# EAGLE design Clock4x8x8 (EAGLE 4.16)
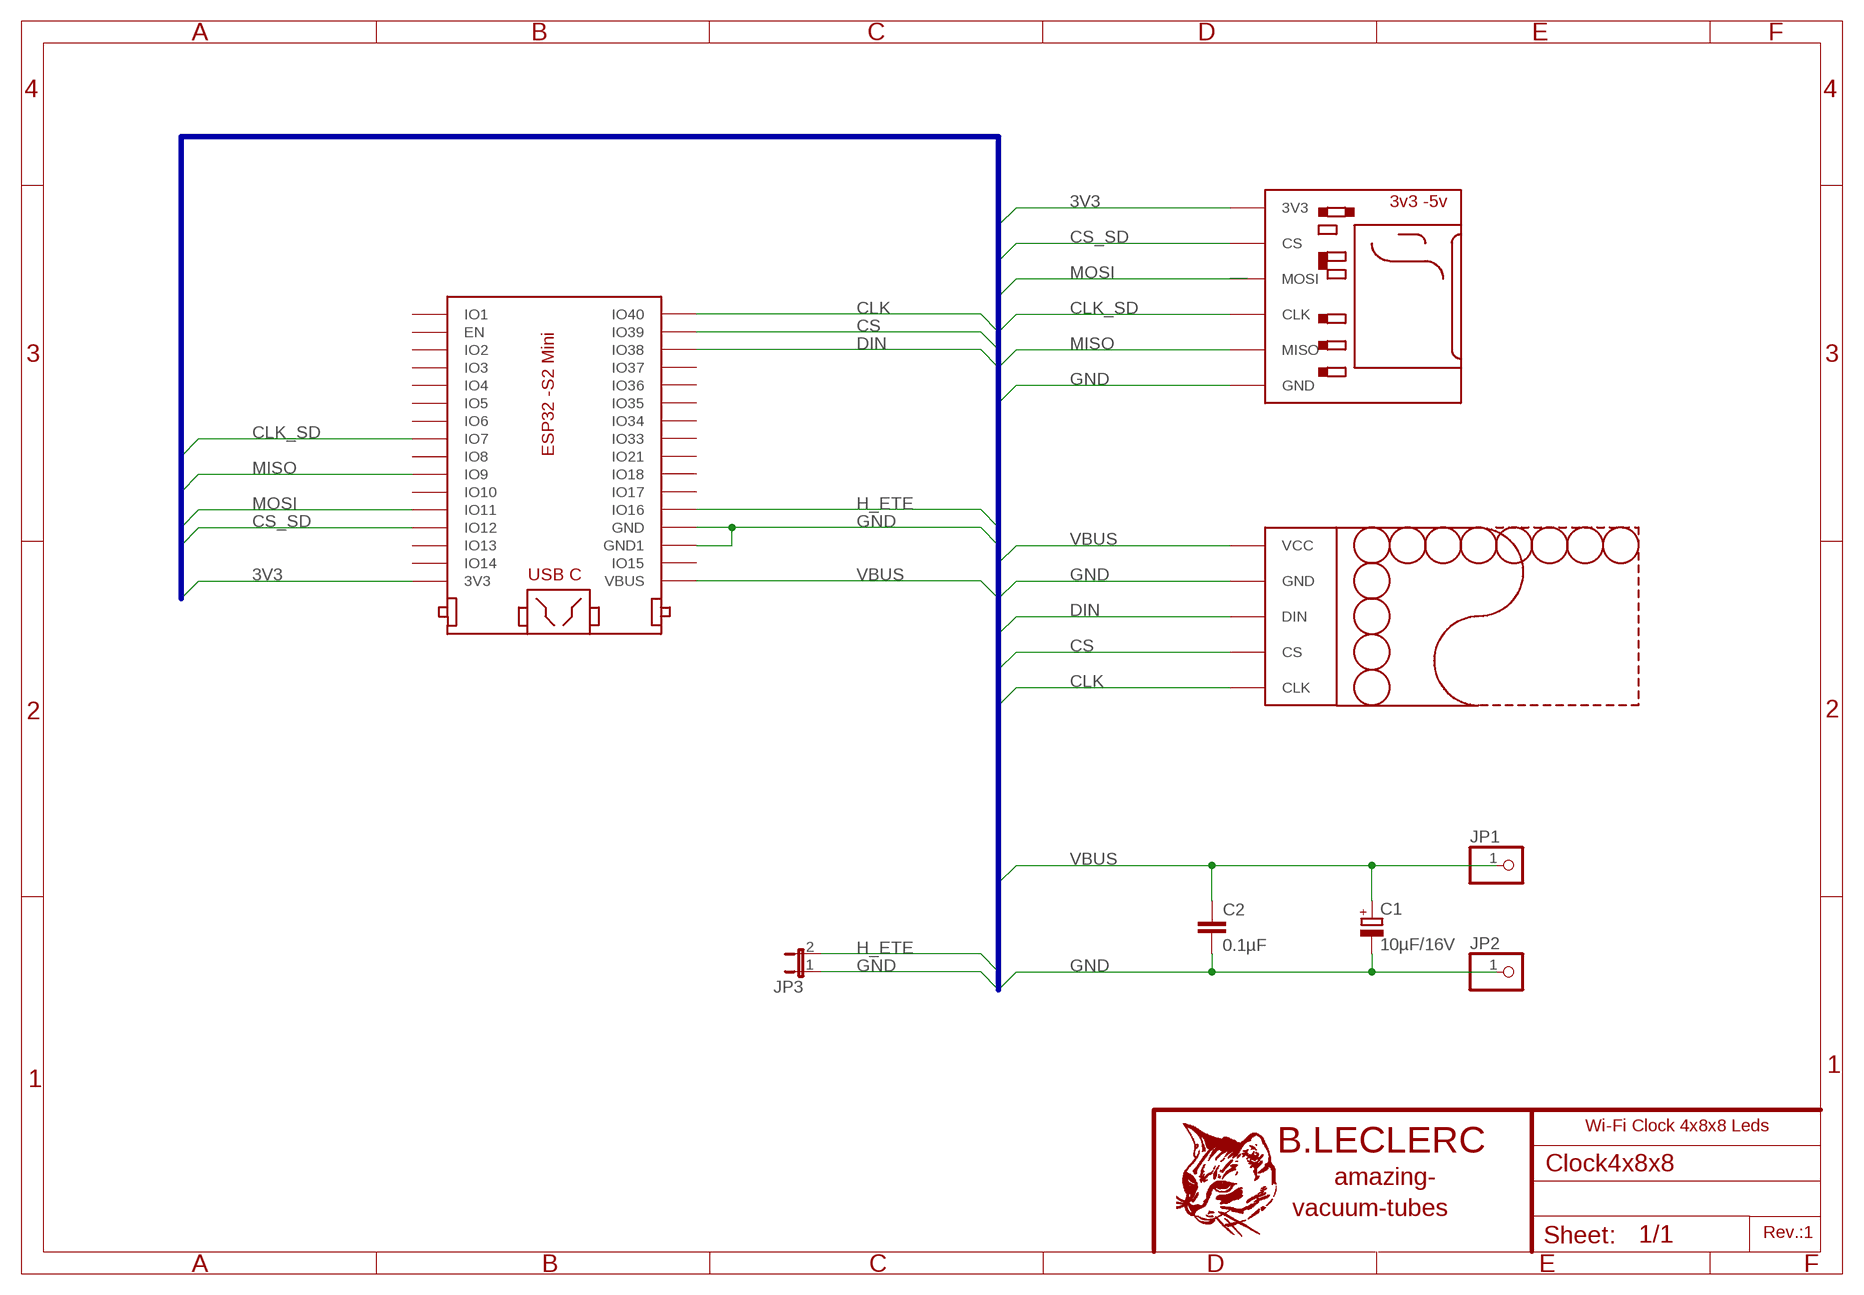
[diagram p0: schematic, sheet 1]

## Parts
C1  10µF/16V  CPOL-EUE5-8.5  [E5-8,5]
C2  0.1µF  C-EU102-043X133  [C102-043X133]
JP1  PINHD-1X1  [1X01]
JP2  PINHD-1X1  [1X01]
JP3  JP1E  [JP1]
U$2  ESP32_S2MINI  [ESP32_S2MINI]
U$3  LECTEUR_MICRO_SD  [LECTEUR_MICRO_SD]
U$4  4DIGITS_8X8_LEDS  [4DIGITS_8X8_LEDS]

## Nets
3V3: U$2.3V3 U$3.3V3
CLK: U$2.IO40 U$4.CLK
CLK_SD: U$2.IO7 U$3.CLK
CS: U$2.IO39 U$4.CS
CS_SD: U$2.IO12 U$3.CS
DIN: U$2.IO38 U$4.DIN
GND: C1.- C2.2 JP2.1 JP3.1 U$2.GND U$2.GND1 U$3.GND U$4.GND
H_ETE: JP3.2 U$2.IO16
MISO: U$2.IO9 U$3.MISO
MOSI: U$2.IO11 U$3.MOSI
VBUS: C1.+ C2.1 JP1.1 U$2.VBUS U$4.VCC
Unconnected: U$2.EN U$2.IO1 U$2.IO2 U$2.IO3 U$2.IO4 U$2.IO5 U$2.IO6 U$2.IO8 U$2.IO10 U$2.IO13 U$2.IO14 U$2.IO15 U$2.IO17 U$2.IO18 U$2.IO21 U$2.IO33 U$2.IO34 U$2.IO35 U$2.IO36 U$2.IO37

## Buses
B$1

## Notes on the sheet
- Wi-Fi Clock 4x8x8 Leds
- Rev.:1

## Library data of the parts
C1 = rcl:CPOL-EU: POLARIZED CAPACITOR, European symbol
C2 = rcl:C-EU: CAPACITOR, European symbol
JP1 JP2 = pinhead:PINHD-1X1: PIN HEADER
JP3 = jumper:JP1E: JUMPER
U$2 = Arduino:ESP32_S2MINI
U$3 = Arduino:LECTEUR_MICRO_SD
U$4 = Arduino:4DIGITS_8X8_LEDS

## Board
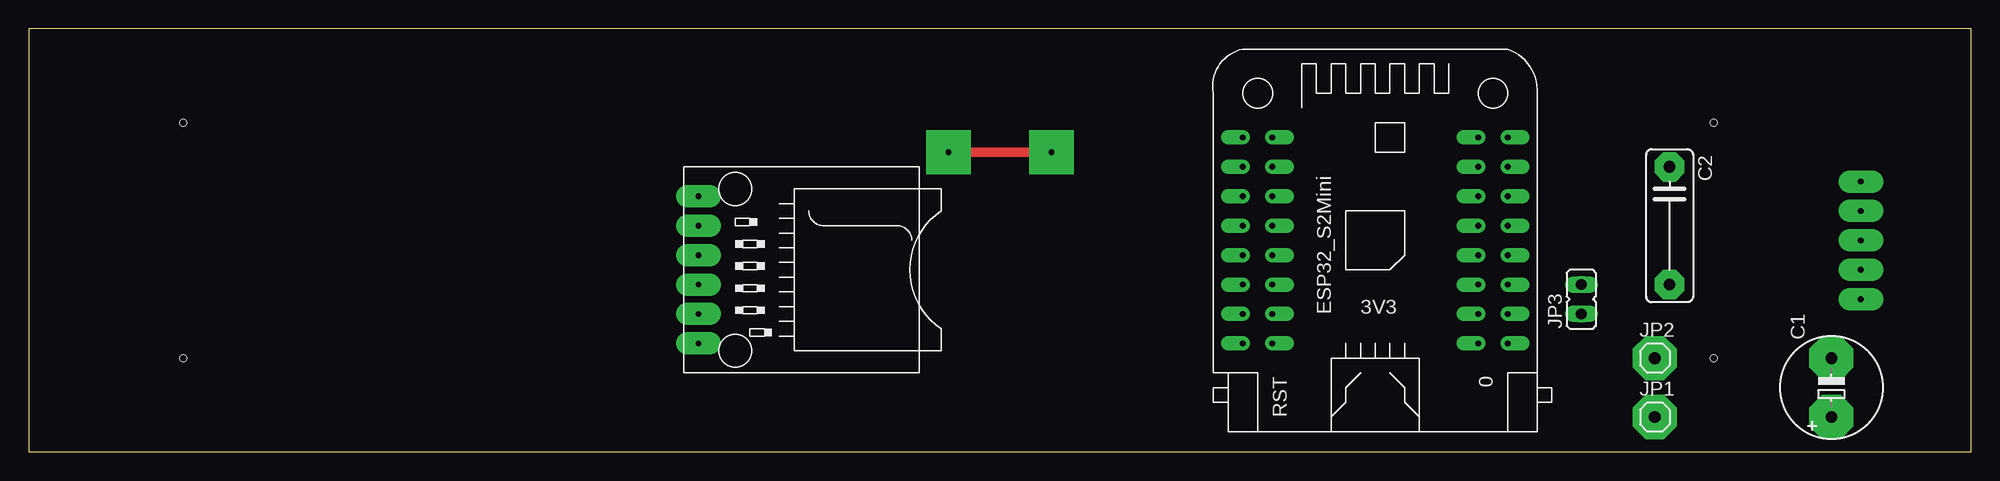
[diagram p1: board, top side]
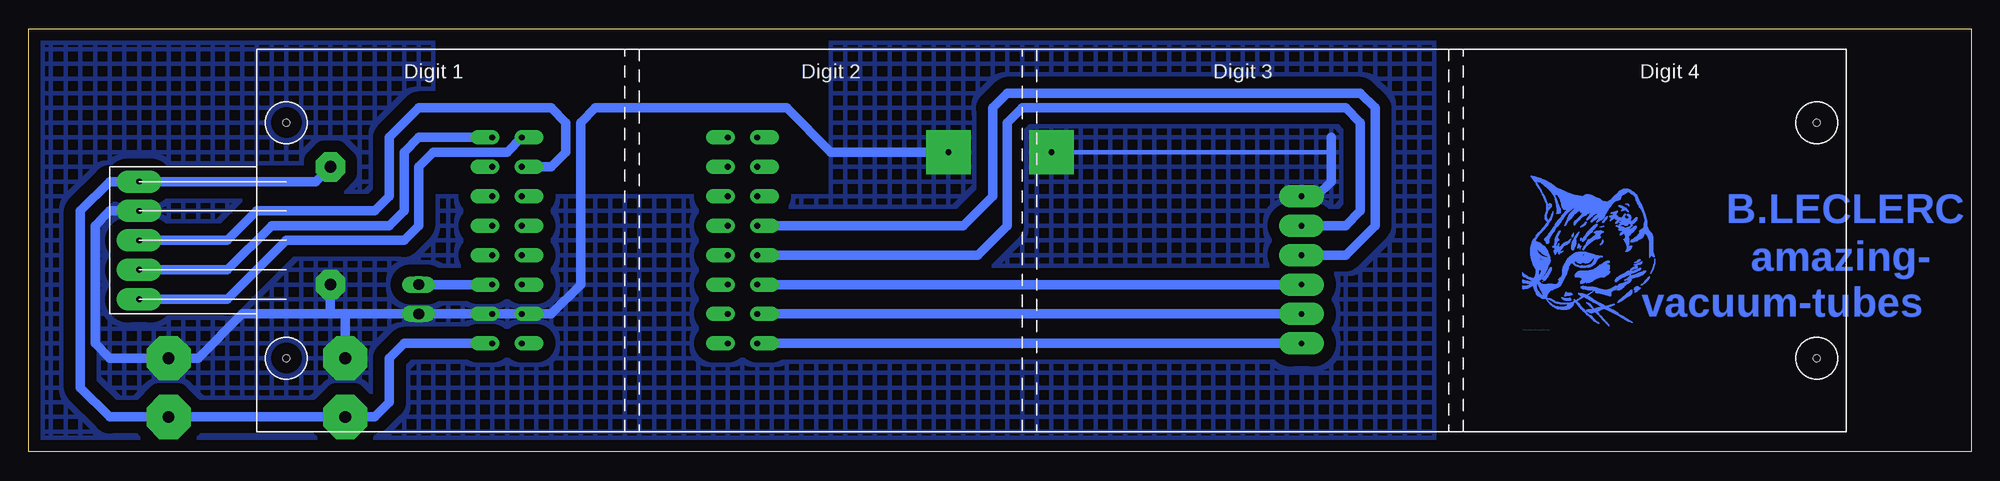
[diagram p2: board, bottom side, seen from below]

Size 167.62 x 36.5 mm. Coordinates in mm from the lower left corner, seen from the top.
Outline: 0,0 167.62,0 167.62,36.5 0,36.5 0,0
Copper layers (1*16): Top 0.035mm / dielectric 1.5mm / Bottom 0.035mm
Design rules "default": minimum track width 10mil, minimum drill 24mil, track to track 8mil, track to pad 8mil, pad to pad 8mil, via to via 8mil, smd to smd 8mil, copper to edge 40mil, drill to drill 8mil, minimum pad ring 10mil, minimum via ring 8mil, stop-mask expansion 4mil, vias tented up to drill 0mil, thermal gap 10mil

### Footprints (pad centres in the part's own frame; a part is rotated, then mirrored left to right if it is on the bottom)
E5-8,5 = drill 1.016 pad 2.54 round: + -2.54,0 | drill 1.016 pad 2.54 octagon: - 2.54,0
C102-043X133 = drill 1.016 octagon: 1 -5.08,0; 2 5.08,0
1X01 = drill 1.016 octagon: 1 0,0
JP1 = drill 0.914 long: 1 0,-1.27; 2 0,1.27
ESP32_S2MINI = drill 0.5 pad 1.27 offset: 3V3 0,0; EN 0,17.78; GND 20.32,2.54; GND1 22.86,2.54; IO1 2.54,17.78; IO2 2.54,15.24; IO3 0,15.24; IO4 2.54,12.7; IO5 0,12.7; IO6 2.54,10.16; IO7 0,10.16; IO8 2.54,7.62; IO9 0,7.62; IO10 2.54,5.08; IO11 0,5.08; IO12 0,2.54; IO13 2.54,2.54; IO14 2.54,0; IO15 20.32,0; IO16 22.86,5.08; IO17 20.32,5.08; IO18 22.86,7.62; IO21 20.32,7.62; IO33 22.86,10.16; IO34 20.32,10.16; IO35 22.86,12.7; IO36 20.32,12.7; IO37 22.86,15.24; IO38 20.32,15.24; IO39 22.86,17.78; IO40 20.32,17.78; VBUS 22.86,0
LECTEUR_MICRO_SD = drill 0.5 pad 1.93 long: 3V3 0,-6.35; CLK 0,1.27; CS 0,-3.81; GND 0,6.35; MISO 0,3.81; MOSI 0,-1.27
4DIGITS_8X8_LEDS = drill 0.5 pad 1.93 long: CLK 12.7,5.08; CS 12.7,2.54; DIN 12.7,0; GND 12.7,-2.54; VCC 12.7,-5.08 | hole 0.6: 0,10.16; 0,-10.16; -132.08,-10.16; -132.08,10.16

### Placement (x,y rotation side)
C1  155.57,5.55 90 top
C2  141.6,19.52 270 top
JP1  140.33,3.01 0 top
JP2  140.33,8.09 0 top
JP3  133.98,13.17 0 top
U$2  104.77,9.36 0 top
U$3  57.78,15.71 0 top
U$4  145.41,18.25 180 bottom
U$5  [CHAT1]  38.73,10.63 0 bottom

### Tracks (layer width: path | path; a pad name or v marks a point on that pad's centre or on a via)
3V3
  Bottom 0.813: U$3.3V3 U$2.3V3
CLK
  Bottom 0.813: U$2.IO40 126.36,25.87 132.71,25.87 133.98,24.6 133.98,19.52 135.25,18.25 145.41,18.25 150.49,13.17 U$4.CLK
CLK_SD
  Bottom 0.813: U$3.CLK 53.97,16.98 51.43,19.52 51.43,29.68 52.7,30.95 83.18,30.95 84.45,29.68 84.45,22.06 86.99,19.52 U$2.IO7
CS
  Bottom 0.813: U$2.IO39 133.98,27.14 135.25,25.87 135.25,20.79 136.52,19.52 146.68,19.52 150.49,15.71 U$4.CS
CS_SD
  Bottom 0.813: U$3.CS U$2.IO12
DIN
  Bottom 0.813: U$4.DIN 150.49,18.25 147.95,20.79 137.79,20.79 136.52,22.06 136.52,27.14 133.98,29.68 122.55,29.68 121.28,28.41 121.28,25.87 122.55,24.6 U$2.IO38
GND  (via drill 0.5 pad 1.42, 0.5 pad 2.54, 0.5 pad 3.81)
  Top 0.813: v79.37,25.87 v88.26,25.87
  Bottom 0.406: 55.24,25.87 v79.37,25.87
  Bottom 0.813: U$4.GND 160.65,20.79 161.92,19.52 161.92,9.36 160.65,8.09 C1.- 153.03,8.09 149.22,11.9 141.6,11.9 | 140.33,11.9 JP3.1 U$2.GND1 U$2.GND 122.55,11.9 120.01,14.44 120.01,28.41 118.74,29.68 102.23,29.68 98.42,25.87 v88.26,25.87 | 140.33,11.9 141.6,11.9 | 141.6,11.9 C2.2 | 140.33,11.9 JP2.1 | U$3.GND 56.51,22.06 55.24,23.33 55.24,25.87 55.24,27.14
  other vias: 133.98,11.9 140.33,8.09 141.6,14.44 155.57,8.09 140.33,8.09
  pour Bottom (isolate 1.016, no thermals, hatched): 167,36.03 167,0.47 46.35,0.47 46.35,36.03 98.42,36.03 98.42,22.06 132.71,22.06 132.71,36.03
H_ETE
  Bottom 0.813: U$2.IO16 JP3.2
MISO
  Bottom 0.813: U$2.IO9 85.72,16.98 83.18,19.52 83.18,28.41 81.91,29.68 53.97,29.68 52.7,28.41 52.7,20.79 53.97,19.52 U$3.MISO
MOSI
  Bottom 0.813: U$3.MOSI U$2.IO11
N$2  (via drill 0.5 pad 3.81)
  other vias: 140.33,3.01
N$3  (via drill 0.5 pad 2.54)
  other vias: 141.6,24.6
N$6  (via drill 0.5 pad 2.54)
  other vias: 140.33,3.01
N$7  (via drill 0.5 pad 1.42)
  other vias: 133.98,14.44
N$9  (via drill 0.5 pad 3.81)
  other vias: 155.57,3.01
VBUS
  Bottom 0.813: JP1.1 C1.+ | JP1.1 160.65,3.01 163.19,5.55 163.19,20.79 160.65,23.33 U$4.VCC 142.87,23.33 C2.1 | U$2.VBUS 135.25,9.36 136.52,8.09 136.52,4.28 137.79,3.01 JP1.1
